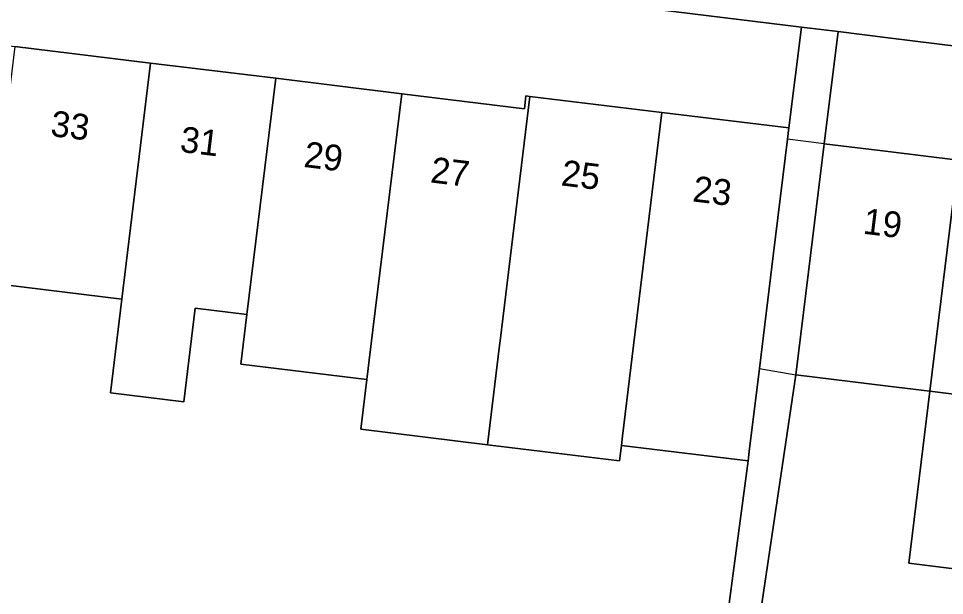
# Model space of a CAD drawing. Extents: x 158086 to 159499, y 382904 to 383981.
# Drawn here: x 158466.28 to 158502.18, y 383222.88 to 383245.25 of the extents above; entities that cross this region are included whole.
import ezdxf

# ---------------------------------------------------------------- set-up
doc = ezdxf.new("R2010")
doc.units = 0
for name, color, linetype in [('IMGEO_Erf', 7, 'Continuous'), ('IMGEO_Pand', 7, 'Continuous'), ('IMGEO_Pand_nummerreeks', 7, 'Continuous'), ('IMGEO_Pand_overbouw', 7, 'Continuous'), ('IMGEO_Voetpad_open', 7, 'Continuous')]:
    doc.layers.add(name, color=color, linetype=linetype)

msp = doc.modelspace()

# ---------------------------------------------------------------- linework, layer by layer
at = {"layer": 'IMGEO_Erf'}
for points in [[(158436.549, 383248.305), (158441.758, 383247.657), (158441.696, 383247.152), (158441.807, 383247.138), (158446.774, 383246.532), (158451.695, 383245.931), (158456.494, 383245.345), (158461.605, 383244.721), (158466.13, 383244.169), (158471.399, 383243.525), (158476.25, 383242.933), (158481.134, 383242.337), (158485.89, 383241.756), (158485.95, 383242.251), (158486.107, 383242.232), (158491.225, 383241.61), (158496.149, 383241.011), (158496.63, 383244.919), (158455.212, 383250), (158436.049, 383252.351)], [(158557.145, 383237.463), (158500, 383244.504), (158498.052, 383244.744), (158497.517, 383240.394), (158500, 383240.091), (158502.71, 383239.761)], [(158493.258, 383218.308), (158494.565, 383228.096), (158489.65, 383228.699), (158489.578, 383228.104), (158484.46, 383228.728), (158479.548, 383229.327), (158479.782, 383231.251), (158474.898, 383231.85), (158475.133, 383233.774), (158473.13, 383234.02), (158472.683, 383230.385), (158469.838, 383230.732), (158470.282, 383234.37), (158465.013, 383235.017)], [(158540.968, 383221.862), (158541.465, 383225.918), (158539.205, 383226.195), (158533.838, 383226.852), (158528.82, 383227.467), (158526.013, 383227.811), (158525.575, 383224.232), (158522.887, 383224.556), (158522.96, 383225.163), (158523.32, 383228.141), (158517.91, 383228.804), (158512.415, 383229.477), (158507.275, 383230.106), (158503.994, 383230.508), (158503.18, 383223.84), (158500.802, 383224.131), (158501.616, 383230.799), (158500, 383230.997), (158496.419, 383231.436), (158494.542, 383218.82)]]:
    msp.add_lwpolyline(points, dxfattribs=at)
at = {"layer": 'IMGEO_Pand'}
for points in [[(158470.282, 383234.37), (158471.399, 383243.525), (158466.13, 383244.169), (158465.013, 383235.017)], [(158470.282, 383234.37), (158469.838, 383230.732), (158472.683, 383230.385), (158473.13, 383234.02), (158475.133, 383233.774), (158476.25, 383242.933), (158471.399, 383243.525)], [(158481.134, 383242.337), (158476.25, 383242.933), (158475.133, 383233.774), (158474.898, 383231.85), (158479.782, 383231.251), (158480.017, 383233.175)], [(158486.107, 383242.232), (158485.95, 383242.251), (158485.89, 383241.756), (158481.134, 383242.337), (158480.017, 383233.175), (158479.782, 383231.251), (158479.548, 383229.327), (158484.46, 383228.728), (158484.93, 383232.572), (158484.951, 383232.755)], [(158490.668, 383237.044), (158491.225, 383241.61), (158486.107, 383242.232), (158484.951, 383232.755), (158484.93, 383232.572), (158484.46, 383228.728), (158489.578, 383228.104), (158489.65, 383228.699), (158489.694, 383229.064)], [(158496.095, 383240.569), (158496.149, 383241.011), (158491.225, 383241.61), (158490.668, 383237.044), (158489.694, 383229.064), (158489.65, 383228.699), (158494.565, 383228.096), (158494.61, 383228.461), (158495.005, 383231.679), (158495.541, 383236.049)], [(158501.616, 383230.799), (158502.71, 383239.761), (158500, 383240.091), (158497.517, 383240.394), (158496.909, 383235.432), (158496.419, 383231.436), (158500, 383230.997)], [(158508.368, 383239.07), (158502.71, 383239.761), (158501.616, 383230.799), (158503.994, 383230.508), (158507.275, 383230.106)], [(158503.994, 383230.508), (158501.616, 383230.799), (158500.802, 383224.131), (158503.18, 383223.84)]]:
    msp.add_lwpolyline(points, close=True, dxfattribs=at)
at = {"layer": 'IMGEO_Pand_overbouw'}
msp.add_lwpolyline([(158497.517, 383240.394), (158496.095, 383240.569), (158495.541, 383236.049), (158495.005, 383231.679), (158496.419, 383231.436), (158496.909, 383235.432)], close=True, dxfattribs=at)
at = {"layer": 'IMGEO_Voetpad_open'}
for points in [[(158277.718, 383271.726), (158339.394, 383264.164), (158340.307, 383264.052), (158345.526, 383263.412), (158350.794, 383262.766), (158350.957, 383262.746), (158353.332, 383262.456), (158436.049, 383252.351), (158455.212, 383250), (158496.63, 383244.919), (158496.962, 383244.878), (158498.052, 383244.744), (158500, 383244.504), (158557.145, 383237.463), (158557.763, 383241.156), (158557.654, 383241.196), (158556.058, 383241.376)], [(158494.542, 383218.82), (158496.419, 383231.436), (158496.909, 383235.432), (158497.517, 383240.394), (158498.052, 383244.744), (158496.962, 383244.878), (158496.63, 383244.919), (158496.149, 383241.011), (158496.095, 383240.569), (158495.541, 383236.049), (158495.005, 383231.679), (158494.61, 383228.461), (158494.565, 383228.096), (158493.258, 383218.308)]]:
    msp.add_lwpolyline(points, dxfattribs=at)

# ---------------------------------------------------------------- texts
at = {"layer": 'IMGEO_Pand_nummerreeks'}
for s, rotation, p in [('33', 353.0388, (158467.485, 383240.699)), ('31', 353.0388, (158472.507, 383240.085)), ('29', 353.0386, (158477.306, 383239.5)), ('27', 353.0386, (158482.216, 383238.9)), ('25', 353.0672, (158487.283, 383238.784)), ('23', 353.0672, (158492.382, 383238.164)), ('19', 353.0502, (158498.988, 383236.912))]:
    msp.add_text(s, height=1, rotation=rotation, dxfattribs=at).set_placement(p)

doc.saveas('drawing.dxf')
